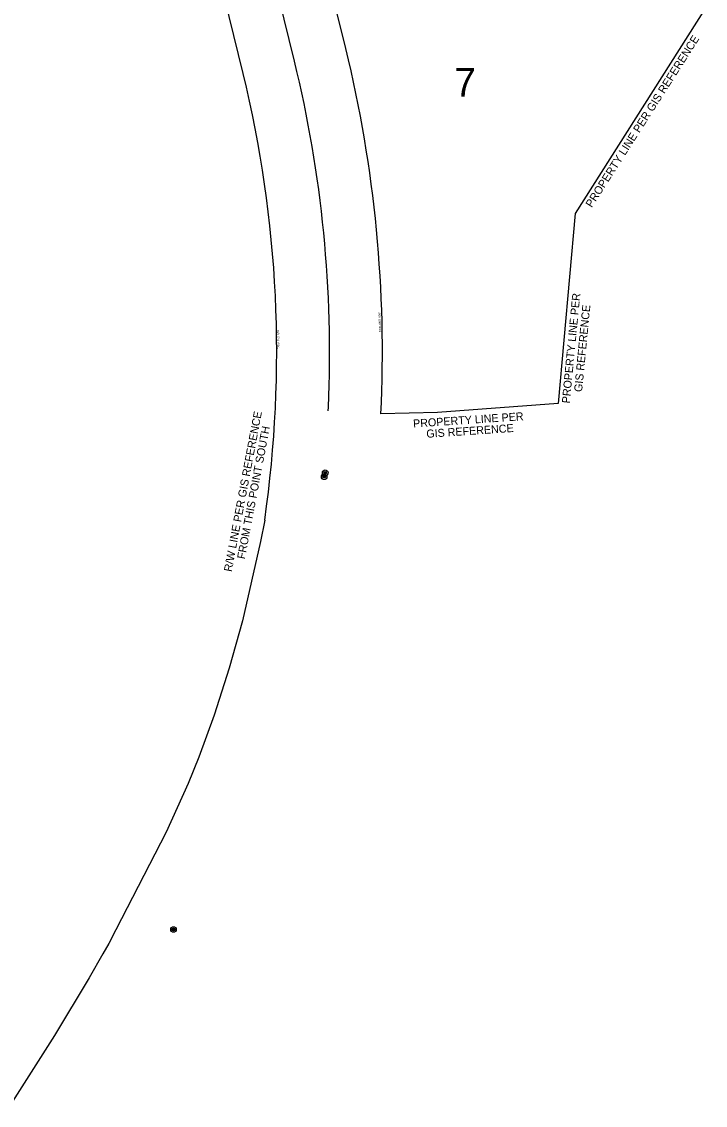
# Model space of a CAD drawing. Extents: x 1398271 to 1401121, y 1018936 to 1022764.
# Drawn here: x 1399686 to 1400113, y 1019153 to 1019830 of the extents above; entities that cross this region are included whole.
import ezdxf

# ---------------------------------------------------------------- set-up
doc = ezdxf.new("R2010")
doc.units = 0
for name, color, linetype in [('RD_EX_DV_Prop', 7, 'Continuous'), ('RD_EX_DV_Prop_txCode', 7, 'Continuous'), ('RD_EX_DV_PropPin', 7, 'Continuous'), ('RD_EX_DV_TX_Prop', 7, 'Continuous'), ('RD_EX_RW', 7, 'Continuous'), ('RD_EX_RW_TX', 7, 'Continuous'), ('RD_HC_Cl', 7, 'Continuous'), ('RD_SMD_Locator', 7, 'Continuous')]:
    doc.layers.add(name, color=color, linetype=linetype)

msp = doc.modelspace()

# ---------------------------------------------------------------- linework, layer by layer
at = {"layer": 'RD_EX_DV_Prop'}
for p, q in [((1400113.42, 1019838.67), (1400032.13, 1019710.47)), ((1400032.13, 1019710.47), (1400021.46, 1019591.94)), ((1400021.46, 1019591.94), (1399946.04, 1019586.21)), ((1399946.04, 1019586.21), (1399910.74, 1019585.36)), ((1399838.15, 1019518.99), (1399835.52, 1019505.67)), ((1399835.52, 1019505.67), (1399824.18, 1019456.11)), ((1399824.18, 1019456.11), (1399816.05, 1019426.43)), ((1399816.05, 1019426.43), (1399806.65, 1019397.16)), ((1399806.65, 1019397.16), (1399796.99, 1019370.92)), ((1399796.99, 1019370.92), (1399790.32, 1019354.45)), ((1399790.32, 1019354.45), (1399776.65, 1019324.05)), ((1399776.65, 1019324.05), (1399745.2, 1019263.02)), ((1399745.2, 1019263.02), (1399740.69, 1019254.6)), ((1399740.69, 1019254.6), (1399737.08, 1019248.14)), ((1399737.08, 1019248.14), (1399728.48, 1019233.08)), ((1399728.48, 1019233.08), (1399706.92, 1019197.12)), ((1399706.92, 1019197.12), (1399679.17, 1019153.41))]:
    msp.add_line(p, q, dxfattribs=at)
at = {"layer": 'RD_EX_DV_PropPin'}
for p, q in [((1399875.22, 1019548.44), (1399875.22, 1019548.84)), ((1399875.25, 1019548.34), (1399875.25, 1019548.94)), ((1399875.29, 1019548.27), (1399875.29, 1019549.01)), ((1399875.32, 1019548.21), (1399875.32, 1019549.07)), ((1399875.36, 1019548.17), (1399875.36, 1019549.11)), ((1399875.39, 1019548.12), (1399875.39, 1019549.15)), ((1399875.43, 1019548.09), (1399875.43, 1019549.19)), ((1399875.46, 1019548.06), (1399875.46, 1019549.22)), ((1399875.5, 1019548.03), (1399875.5, 1019549.25)), ((1399875.53, 1019548.01), (1399875.53, 1019549.27)), ((1399875.57, 1019547.98), (1399875.57, 1019549.3)), ((1399875.6, 1019547.96), (1399875.6, 1019549.32)), ((1399875.64, 1019547.95), (1399875.64, 1019549.33)), ((1399875.67, 1019547.93), (1399875.67, 1019549.35)), ((1399875.71, 1019547.92), (1399875.71, 1019549.36)), ((1399875.74, 1019547.91), (1399875.74, 1019549.37)), ((1399875.78, 1019547.9), (1399875.78, 1019549.38)), ((1399875.81, 1019547.89), (1399875.81, 1019549.39)), ((1399875.85, 1019547.89), (1399875.85, 1019549.39)), ((1399875.88, 1019547.88), (1399875.88, 1019549.4)), ((1399875.92, 1019547.88), (1399875.92, 1019549.4)), ((1399875.95, 1019547.88), (1399875.95, 1019549.4)), ((1399875.99, 1019547.88), (1399875.99, 1019549.4)), ((1399876.02, 1019547.88), (1399876.02, 1019549.4)), ((1399876.06, 1019547.89), (1399876.06, 1019549.39)), ((1399876.09, 1019547.89), (1399876.09, 1019549.39)), ((1399876.13, 1019547.9), (1399876.13, 1019549.38)), ((1399876.16, 1019547.91), (1399876.16, 1019549.37)), ((1399876.2, 1019547.92), (1399876.2, 1019549.36)), ((1399876.23, 1019547.93), (1399876.23, 1019549.35)), ((1399876.27, 1019547.95), (1399876.27, 1019549.33)), ((1399876.3, 1019547.96), (1399876.3, 1019549.32)), ((1399876.34, 1019547.98), (1399876.34, 1019549.3)), ((1399876.37, 1019548.01), (1399876.37, 1019549.27)), ((1399876.41, 1019548.03), (1399876.41, 1019549.25)), ((1399876.44, 1019548.06), (1399876.44, 1019549.22)), ((1399876.48, 1019548.09), (1399876.48, 1019549.19)), ((1399876.51, 1019548.12), (1399876.51, 1019549.15)), ((1399876.55, 1019548.17), (1399876.55, 1019549.11)), ((1399876.58, 1019548.21), (1399876.58, 1019549.07)), ((1399876.62, 1019548.27), (1399876.62, 1019549.01)), ((1399876.65, 1019548.34), (1399876.65, 1019548.94)), ((1399876.69, 1019548.44), (1399876.69, 1019548.84)), ((1399874.56, 1019545.9), (1399874.56, 1019546.29)), ((1399874.59, 1019545.8), (1399874.59, 1019546.39)), ((1399874.63, 1019545.73), (1399874.63, 1019546.46)), ((1399874.66, 1019545.67), (1399874.66, 1019546.52)), ((1399874.7, 1019545.62), (1399874.7, 1019546.57)), ((1399874.73, 1019545.58), (1399874.73, 1019546.61)), ((1399874.77, 1019545.54), (1399874.77, 1019546.65)), ((1399874.8, 1019545.51), (1399874.8, 1019546.68)), ((1399874.84, 1019545.49), (1399874.84, 1019546.7)), ((1399874.87, 1019545.46), (1399874.87, 1019546.73)), ((1399874.91, 1019545.44), (1399874.91, 1019546.75)), ((1399874.94, 1019545.42), (1399874.94, 1019546.77)), ((1399874.98, 1019545.4), (1399874.98, 1019546.79)), ((1399875.01, 1019545.39), (1399875.01, 1019546.8)), ((1399875.05, 1019545.37), (1399875.05, 1019546.82)), ((1399875.08, 1019545.36), (1399875.08, 1019546.83)), ((1399875.12, 1019545.35), (1399875.12, 1019546.84)), ((1399875.15, 1019545.35), (1399875.15, 1019546.84)), ((1399875.19, 1019545.34), (1399875.19, 1019546.85)), ((1399875.22, 1019545.34), (1399875.22, 1019546.85)), ((1399875.26, 1019545.33), (1399875.26, 1019546.86)), ((1399875.29, 1019545.33), (1399875.29, 1019546.86)), ((1399875.33, 1019545.33), (1399875.33, 1019546.86)), ((1399875.36, 1019545.34), (1399875.36, 1019546.85)), ((1399875.4, 1019545.34), (1399875.4, 1019546.85)), ((1399875.43, 1019545.35), (1399875.43, 1019546.84)), ((1399875.47, 1019545.35), (1399875.47, 1019546.84)), ((1399875.5, 1019545.36), (1399875.5, 1019546.83)), ((1399875.54, 1019545.37), (1399875.54, 1019546.82)), ((1399875.57, 1019545.39), (1399875.57, 1019546.8)), ((1399875.61, 1019545.4), (1399875.61, 1019546.79)), ((1399875.64, 1019545.42), (1399875.64, 1019546.77)), ((1399875.68, 1019545.44), (1399875.68, 1019546.75)), ((1399875.71, 1019545.46), (1399875.71, 1019546.73)), ((1399875.75, 1019545.49), (1399875.75, 1019546.7)), ((1399875.78, 1019545.51), (1399875.78, 1019546.68)), ((1399875.82, 1019545.54), (1399875.82, 1019546.65)), ((1399875.85, 1019545.58), (1399875.85, 1019546.61)), ((1399875.89, 1019545.62), (1399875.89, 1019546.57)), ((1399875.92, 1019545.67), (1399875.92, 1019546.52)), ((1399875.96, 1019545.73), (1399875.96, 1019546.46)), ((1399875.99, 1019545.8), (1399875.99, 1019546.39)), ((1399876.03, 1019545.9), (1399876.03, 1019546.29)), ((1399780.42, 1019263.07), (1399780.42, 1019263.47)), ((1399780.46, 1019262.97), (1399780.46, 1019263.57)), ((1399780.49, 1019262.9), (1399780.49, 1019263.64)), ((1399780.53, 1019262.84), (1399780.53, 1019263.7)), ((1399780.56, 1019262.8), (1399780.56, 1019263.74)), ((1399780.6, 1019262.75), (1399780.6, 1019263.78)), ((1399780.63, 1019262.72), (1399780.63, 1019263.82)), ((1399780.67, 1019262.69), (1399780.67, 1019263.85)), ((1399780.7, 1019262.66), (1399780.7, 1019263.88)), ((1399780.74, 1019262.63), (1399780.74, 1019263.9)), ((1399780.77, 1019262.61), (1399780.77, 1019263.93)), ((1399780.81, 1019262.59), (1399780.81, 1019263.95)), ((1399780.84, 1019262.58), (1399780.84, 1019263.96)), ((1399780.88, 1019262.56), (1399780.88, 1019263.98)), ((1399780.91, 1019262.55), (1399780.91, 1019263.99)), ((1399780.95, 1019262.54), (1399780.95, 1019264)), ((1399780.98, 1019262.53), (1399780.98, 1019264.01)), ((1399781.02, 1019262.52), (1399781.02, 1019264.02)), ((1399781.05, 1019262.52), (1399781.05, 1019264.02)), ((1399781.09, 1019262.51), (1399781.09, 1019264.03)), ((1399781.12, 1019262.51), (1399781.12, 1019264.03)), ((1399781.16, 1019262.51), (1399781.16, 1019264.03)), ((1399781.19, 1019262.51), (1399781.19, 1019264.03)), ((1399781.23, 1019262.51), (1399781.23, 1019264.03)), ((1399781.26, 1019262.52), (1399781.26, 1019264.02)), ((1399781.3, 1019262.52), (1399781.3, 1019264.02)), ((1399781.33, 1019262.53), (1399781.33, 1019264.01)), ((1399781.37, 1019262.54), (1399781.37, 1019264)), ((1399781.4, 1019262.55), (1399781.4, 1019263.99)), ((1399781.44, 1019262.56), (1399781.44, 1019263.98)), ((1399781.47, 1019262.58), (1399781.47, 1019263.96)), ((1399781.51, 1019262.59), (1399781.51, 1019263.95)), ((1399781.54, 1019262.61), (1399781.54, 1019263.93)), ((1399781.58, 1019262.63), (1399781.58, 1019263.9)), ((1399781.61, 1019262.66), (1399781.61, 1019263.88)), ((1399781.65, 1019262.69), (1399781.65, 1019263.85)), ((1399781.68, 1019262.72), (1399781.68, 1019263.82)), ((1399781.72, 1019262.75), (1399781.72, 1019263.78)), ((1399781.75, 1019262.8), (1399781.75, 1019263.74)), ((1399781.79, 1019262.84), (1399781.79, 1019263.7)), ((1399781.82, 1019262.9), (1399781.82, 1019263.64)), ((1399781.86, 1019262.97), (1399781.86, 1019263.57)), ((1399781.89, 1019263.07), (1399781.89, 1019263.47))]:
    msp.add_line(p, q, dxfattribs=at)
for centre, radius in [((1399875.29, 1019546.09), 1.75), ((1399875.95, 1019548.64), 1.75), ((1399875.95, 1019548.64), 0.761), ((1399875.29, 1019546.09), 0.761), ((1399781.16, 1019263.27), 1.75), ((1399781.16, 1019263.27), 0.761)]:
    msp.add_circle(centre, radius, dxfattribs=at)
at = {"layer": 'RD_EX_RW'}
for p, q in [((1399888.77, 1019813.66), (1399777.61, 1020268.22)), ((1399824.66, 1019797.98), (1399713.5, 1020252.54))]:
    msp.add_line(p, q, dxfattribs=at)
for radius, start in [(799.58, 357.25057), (733.58, 351.79243)]:
    msp.add_arc((1399112.08, 1019623.72), radius, start, 13.74255, dxfattribs=at)
at = {"layer": 'RD_HC_Cl'}
for p, q in [((1399856.72, 1019805.82), (1399745.55, 1020260.38)), ((1399877.8, 1019587.37), (1399877.9, 1019589.58))]:
    msp.add_line(p, q, dxfattribs=at)
msp.add_arc((1399112.08, 1019623.72), 766.58, 357.44801, 13.74255, dxfattribs=at)
at = {"layer": 'RD_SMD_Locator'}
for centre in [(1399875.95, 1019548.64), (1399875.29, 1019546.09), (1399781.16, 1019263.27)]:
    msp.add_circle(centre, 0.15, dxfattribs=at)

# ---------------------------------------------------------------- texts
at = {"layer": 'RD_EX_DV_Prop_txCode'}
for s, rotation, p in [('PROPERTY LINE PER GIS REFERENCE', 57.51524, (1400042.45, 1019713.88)), ('PROPERTY LINE PER', 84.47007, (1400028.71, 1019591.78)), ('GIS REFERENCE', 84.47007, (1400036.37, 1019598.89)), ('R/W LINE PER GIS REFERENCE', 79.26767, (1399817.49, 1019486.47)), ('PROPERTY LINE PER', 3.8582, (1399931.02, 1019576.82)), ('FROM THIS POINT SOUTH', 79.26767, (1399825.73, 1019494.38)), ('GIS REFERENCE', 3.8582, (1399939.29, 1019570.42))]:
    msp.add_text(s, height=5, rotation=rotation, dxfattribs=at).set_placement(p)
at = {"layer": 'RD_EX_DV_TX_Prop'}
msp.add_text('7', height=18, dxfattribs=at).set_placement((1399956.64, 1019783.53))
at = {"layer": 'RD_EX_RW_TX'}
for rotation, p in [(92.11852, (1399910.92, 1019636.51)), (90.86317, (1399847.34, 1019625.7))]:
    msp.add_text('EXISTING R/W', height=1.28, rotation=rotation, dxfattribs=at).set_placement(p)

doc.saveas('drawing.dxf')
